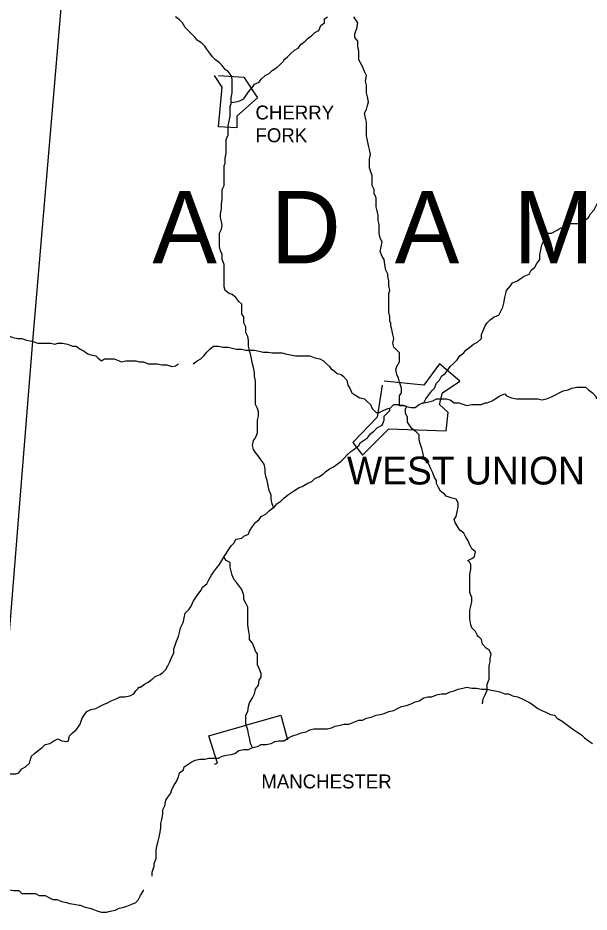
# Model space of a CAD drawing. Extents: x 0 to 34, y 0 to 22.
# Drawn here: x 3.578 to 4.378, y 16.05 to 17.302 of the extents above; entities that cross this region are included whole.
import ezdxf

# ---------------------------------------------------------------- set-up
doc = ezdxf.new("R2010")
doc.units = 0
doc.layers.add('Default', color=7, linetype='Continuous')
doc.layers.add('TR_Turning_Path1', color=7, linetype='Continuous')

msp = doc.modelspace()

# ---------------------------------------------------------------- linework, layer by layer
at = {"layer": 'Default'}
for points in [[(3.6789, 17.7858), (3.6516, 17.4749), (3.5985, 16.8491), (3.5507, 16.2615), (3.5412, 16.0883), (3.5398, 16.0652)], [(3.8766, 17.1832), (3.8766, 17.19), (3.878, 17.1968), (3.878, 17.2023), (3.878, 17.2091), (3.878, 17.2159), (3.8766, 17.2213), (3.8725, 17.2268), (3.8684, 17.2295), (3.8643, 17.235), (3.8602, 17.2391), (3.8548, 17.2432), (3.8507, 17.2473), (3.8452, 17.2541), (3.8425, 17.2582), (3.8398, 17.2623), (3.8357, 17.2663), (3.8289, 17.2704), (3.8261, 17.2745), (3.8207, 17.28), (3.8166, 17.2841), (3.8125, 17.2882), (3.8084, 17.295), (3.8043, 17.2991), (3.7989, 17.3032)], [(3.9502, 17.2432), (3.9557, 17.2473), (3.9598, 17.2513), (3.9652, 17.2568), (3.9707, 17.2595), (3.9748, 17.265), (3.9802, 17.2691), (3.9843, 17.2732), (3.9898, 17.2772), (3.9938, 17.2813), (3.9993, 17.2841), (4.002, 17.2909), (4.0075, 17.295), (4.0075, 17.3004), (4.0116, 17.3032)], [(4.0661, 17.1559), (4.0647, 17.1614), (4.0634, 17.1682), (4.0661, 17.1736), (4.0675, 17.1791), (4.0688, 17.1845), (4.0675, 17.1914), (4.0661, 17.1968), (4.0661, 17.2023), (4.0661, 17.2077), (4.0647, 17.2132), (4.0661, 17.2213), (4.0634, 17.2268), (4.0607, 17.2336), (4.0579, 17.2391), (4.0552, 17.2432), (4.0552, 17.25), (4.0552, 17.2554), (4.0538, 17.2623), (4.0538, 17.2691), (4.0497, 17.2745), (4.0497, 17.28), (4.0525, 17.2868), (4.0538, 17.295), (4.0511, 17.2991), (4.0484, 17.3032)], [(3.8766, 17.1832), (3.8834, 17.1845), (3.8889, 17.1859), (3.8943, 17.1886), (3.897, 17.1927), (3.9011, 17.1982), (3.9066, 17.205), (3.9093, 17.2091), (3.9161, 17.2118), (3.9189, 17.2159), (3.9243, 17.2213), (3.9298, 17.2241), (3.9339, 17.2282), (3.9407, 17.2323), (3.9448, 17.2363), (3.9502, 17.2418), (3.9502, 17.2432)], [(3.8589, 17.2213), (3.8943, 17.2186), (3.9134, 17.19), (3.8848, 17.1641), (3.8848, 17.1477), (3.8589, 17.1491), (3.8643, 17.205), (3.8534, 17.2213)], [(3.8602, 17.0005), (3.863, 17.0059), (3.8643, 17.0114), (3.863, 17.0168), (3.8616, 17.0223), (3.8616, 17.0277), (3.863, 17.0346), (3.863, 17.0414), (3.8643, 17.0482), (3.8643, 17.055), (3.8643, 17.0618), (3.867, 17.0673), (3.867, 17.0741), (3.867, 17.0809), (3.867, 17.0877), (3.867, 17.0946), (3.8684, 17.0986), (3.8684, 17.1055), (3.8698, 17.1123), (3.8698, 17.1191), (3.8698, 17.1245), (3.8698, 17.1314), (3.8725, 17.1382), (3.8725, 17.145), (3.8725, 17.1505), (3.8739, 17.1573), (3.8752, 17.1641), (3.8752, 17.1695), (3.8752, 17.1777), (3.8766, 17.1818), (3.8766, 17.1832)], [(4.077, 17.055), (4.077, 17.0618), (4.0743, 17.0673), (4.0743, 17.0741), (4.0743, 17.0809), (4.0716, 17.0877), (4.0702, 17.0918), (4.0702, 17.0986), (4.0702, 17.1041), (4.0716, 17.1109), (4.0702, 17.1177), (4.0688, 17.1232), (4.0675, 17.13), (4.0661, 17.1368), (4.0661, 17.1423), (4.0661, 17.1491), (4.0661, 17.1545), (4.0661, 17.1545), (4.0661, 17.1559)], [(4.3415, 17.0087), (4.3483, 17.0127), (4.3524, 17.0141), (4.3606, 17.0141), (4.3661, 17.0141), (4.3715, 17.0182), (4.377, 17.0223), (4.3797, 17.0277), (4.3851, 17.0332), (4.3879, 17.0387), (4.3906, 17.0441), (4.3933, 17.0496), (4.3988, 17.0536), (4.4029, 17.0577), (4.407, 17.0632), (4.4097, 17.07), (4.4138, 17.0741), (4.4179, 17.0796), (4.422, 17.085), (4.422, 17.0891)], [(4.0961, 16.9432), (4.0934, 16.9487), (4.092, 16.9568), (4.0907, 16.9637), (4.0879, 16.9678), (4.0852, 16.9746), (4.0866, 16.9814), (4.0879, 16.9882), (4.0852, 16.9937), (4.0838, 17.0005), (4.0838, 17.0059), (4.0838, 17.0127), (4.0825, 17.0182), (4.0825, 17.025), (4.0811, 17.0318), (4.0797, 17.0373), (4.0797, 17.0441), (4.0797, 17.0496), (4.0784, 17.0536), (4.077, 17.055)], [(3.9025, 16.8369), (3.9011, 16.8423), (3.9011, 16.8505), (3.8998, 16.856), (3.897, 16.8614), (3.897, 16.8696), (3.8943, 16.875), (3.8943, 16.8832), (3.8916, 16.8873), (3.8916, 16.8941), (3.8916, 16.9009), (3.8875, 16.905), (3.8834, 16.9105), (3.878, 16.9146), (3.8739, 16.9159), (3.8684, 16.92), (3.867, 16.9255), (3.867, 16.9323), (3.867, 16.9391), (3.867, 16.9446), (3.867, 16.9514), (3.867, 16.9568), (3.8643, 16.9637), (3.8643, 16.9705), (3.8616, 16.9759), (3.8602, 16.9814), (3.8602, 16.9882), (3.8602, 16.995), (3.8602, 16.9991), (3.8602, 17.0005)], [(4.3088, 16.9705), (4.3102, 16.9773), (4.3115, 16.9841), (4.3143, 16.9896), (4.317, 16.995), (4.3197, 17.0005), (4.3252, 17.0005), (4.3333, 17.0046), (4.3374, 17.0073), (4.3415, 17.0087), (4.3415, 17.0087)], [(4.2447, 16.8832), (4.2515, 16.8859), (4.2543, 16.8914), (4.257, 16.8969), (4.2584, 16.9023), (4.2597, 16.9105), (4.2611, 16.9159), (4.2624, 16.92), (4.2679, 16.9269), (4.2706, 16.9309), (4.2774, 16.9337), (4.2815, 16.9364), (4.287, 16.9405), (4.2938, 16.9432), (4.2965, 16.9487), (4.302, 16.9528), (4.3047, 16.9582), (4.3088, 16.9637), (4.3088, 16.9691), (4.3088, 16.9705), (4.3088, 16.9705)], [(4.0988, 16.8764), (4.0988, 16.8832), (4.0975, 16.89), (4.0975, 16.8969), (4.0975, 16.9023), (4.0975, 16.9078), (4.0975, 16.9159), (4.0988, 16.92), (4.0975, 16.9269), (4.0975, 16.9337), (4.0961, 16.9405), (4.0961, 16.9432), (4.0961, 16.9432)], [(3.5098, 16.8778), (3.5167, 16.8737), (3.5235, 16.8709), (3.5289, 16.8669), (3.5344, 16.8669), (3.5398, 16.8641), (3.5466, 16.8614), (3.5521, 16.86), (3.5589, 16.8587), (3.5644, 16.8573), (3.5712, 16.8546), (3.578, 16.8532), (3.5835, 16.8532), (3.5903, 16.8505), (3.5971, 16.8491), (3.5985, 16.8491)], [(4.1125, 16.7591), (4.1125, 16.766), (4.1125, 16.7728), (4.1152, 16.7769), (4.1152, 16.7837), (4.1125, 16.7919), (4.1111, 16.7973), (4.1084, 16.8028), (4.107, 16.8096), (4.1084, 16.8137), (4.1125, 16.8205), (4.1125, 16.826), (4.1125, 16.8328), (4.1084, 16.8369), (4.1043, 16.841), (4.1029, 16.8464), (4.1043, 16.8532), (4.1029, 16.8587), (4.1016, 16.8655), (4.1002, 16.8709), (4.1002, 16.875), (4.0988, 16.8764)], [(4.1466, 16.7632), (4.1493, 16.7687), (4.1534, 16.7741), (4.1575, 16.7796), (4.1615, 16.7837), (4.1643, 16.7905), (4.1684, 16.7946), (4.1711, 16.8001), (4.1765, 16.8041), (4.1806, 16.8096), (4.1834, 16.8137), (4.1875, 16.8178), (4.1929, 16.8232), (4.197, 16.8287), (4.2025, 16.8328), (4.2052, 16.8369), (4.2106, 16.841), (4.2161, 16.845), (4.2215, 16.8478), (4.227, 16.8532), (4.227, 16.8587), (4.2297, 16.8641), (4.2324, 16.8709), (4.2352, 16.875), (4.2393, 16.8791), (4.2447, 16.8832), (4.2447, 16.8832), (4.2447, 16.8832)], [(3.5985, 16.8491), (3.6053, 16.8464), (3.6107, 16.8464), (3.6175, 16.8464), (3.6244, 16.8464), (3.6298, 16.845), (3.6339, 16.8464), (3.6407, 16.8464), (3.6475, 16.845), (3.6544, 16.8423), (3.6598, 16.8423), (3.6653, 16.8382), (3.6707, 16.8355), (3.6762, 16.8314), (3.6803, 16.83), (3.6871, 16.8287), (3.6898, 16.826), (3.6953, 16.8219), (3.6993, 16.8246), (3.7062, 16.8246), (3.713, 16.8246), (3.7198, 16.8219), (3.7225, 16.8205)], [(3.8234, 16.8178), (3.8289, 16.8219), (3.8343, 16.8246), (3.8384, 16.8287), (3.8425, 16.8341), (3.8466, 16.8382), (3.8521, 16.8423), (3.8589, 16.8423), (3.8657, 16.841), (3.8725, 16.841), (3.878, 16.8396), (3.8848, 16.8382), (3.8916, 16.8382), (3.897, 16.8369), (3.9011, 16.8369), (3.9025, 16.8369)], [(3.9134, 16.7305), (3.9134, 16.7387), (3.9148, 16.7442), (3.9148, 16.751), (3.9134, 16.7551), (3.9107, 16.7605), (3.9107, 16.7687), (3.9107, 16.7741), (3.9107, 16.781), (3.9107, 16.7878), (3.9107, 16.7932), (3.9093, 16.8001), (3.9093, 16.8055), (3.908, 16.8123), (3.9066, 16.8178), (3.9052, 16.8246), (3.9039, 16.8314), (3.9025, 16.8355), (3.9025, 16.8369)], [(3.9025, 16.8369), (3.9093, 16.8369), (3.9161, 16.8355), (3.9216, 16.8341), (3.9284, 16.8341), (3.9339, 16.8328), (3.942, 16.8328), (3.9475, 16.8328), (3.9529, 16.8314), (3.9598, 16.83), (3.9666, 16.8287), (3.9734, 16.8287), (3.9802, 16.8287), (3.987, 16.8287), (3.987, 16.8287)], [(3.7225, 16.8205), (3.7293, 16.8219), (3.7362, 16.8219), (3.743, 16.8219), (3.7484, 16.8205), (3.7539, 16.8205), (3.7607, 16.8178), (3.7689, 16.8178), (3.773, 16.8178), (3.7798, 16.8164), (3.7866, 16.8164), (3.7934, 16.8137), (3.7989, 16.815), (3.803, 16.8178), (3.803, 16.8178)], [(3.987, 16.8287), (3.9938, 16.826), (4.0007, 16.8246), (4.0061, 16.8219), (4.0102, 16.8178), (4.0143, 16.8137), (4.017, 16.8096), (4.0184, 16.8096)], [(4.0184, 16.8096), (4.0252, 16.8041), (4.0307, 16.8028), (4.0334, 16.8001), (4.0388, 16.7946), (4.0402, 16.7878), (4.0429, 16.7837), (4.0457, 16.7769), (4.0497, 16.7741), (4.0566, 16.7701), (4.0634, 16.7687), (4.0675, 16.7646), (4.0716, 16.7605), (4.0743, 16.7551), (4.0797, 16.7496), (4.0838, 16.7496), (4.0893, 16.7523), (4.0961, 16.7551), (4.0988, 16.7551)], [(4.0879, 16.7878), (4.0811, 16.7428), (4.047, 16.7073), (4.0607, 16.6896), (4.0975, 16.7264), (4.1779, 16.7237), (4.1806, 16.7496), (4.1684, 16.7605), (4.1725, 16.7769), (4.197, 16.7932), (4.1684, 16.8178), (4.1466, 16.7878), (4.0907, 16.7932)], [(4.287, 16.7687), (4.2924, 16.7687), (4.3006, 16.7687), (4.3061, 16.7687), (4.3115, 16.7673), (4.3183, 16.7687), (4.3252, 16.7714), (4.3306, 16.7741), (4.3361, 16.7769), (4.3415, 16.7796), (4.3483, 16.781), (4.3538, 16.7837), (4.3606, 16.7851), (4.3674, 16.7851), (4.3729, 16.7851), (4.377, 16.781), (4.3824, 16.7769), (4.3879, 16.7714), (4.3879, 16.7687)], [(4.2352, 16.7632), (4.242, 16.766), (4.2461, 16.7687), (4.2529, 16.7728), (4.2597, 16.7755), (4.2624, 16.7728), (4.2693, 16.7701), (4.2761, 16.7687), (4.2815, 16.7687), (4.287, 16.7687)], [(4.0988, 16.7551), (4.1043, 16.7605), (4.1097, 16.7605), (4.1125, 16.7591)], [(4.0988, 16.7551), (4.1043, 16.7605), (4.1097, 16.7605), (4.1125, 16.7591)], [(4.122, 16.7578), (4.1288, 16.7564), (4.1343, 16.7564), (4.1397, 16.7605), (4.1452, 16.7632), (4.1466, 16.7632)], [(4.122, 16.7578), (4.1288, 16.7564), (4.1343, 16.7564), (4.1397, 16.7605), (4.1452, 16.7632), (4.1466, 16.7632)], [(4.1466, 16.7632), (4.1534, 16.7646), (4.1588, 16.766), (4.1643, 16.7687), (4.1711, 16.7687), (4.1779, 16.7687), (4.1834, 16.7673), (4.1888, 16.7632), (4.1956, 16.7632), (4.2025, 16.7605), (4.2065, 16.7591), (4.2134, 16.7605), (4.2202, 16.7605), (4.227, 16.7605), (4.2324, 16.7632), (4.2352, 16.7632), (4.2352, 16.7632)], [(3.9366, 16.616), (3.9407, 16.6214), (3.9461, 16.6255), (3.9502, 16.6296), (3.9557, 16.6337), (3.9598, 16.6364), (3.9652, 16.6405), (3.972, 16.6446), (3.9761, 16.646), (3.9829, 16.6501), (3.9898, 16.6528), (3.9938, 16.6569), (3.9993, 16.6596), (4.0061, 16.6637), (4.0088, 16.6664), (4.0143, 16.6705), (4.0198, 16.6733), (4.0252, 16.6773), (4.0307, 16.6814), (4.0348, 16.6855), (4.0388, 16.6896), (4.0443, 16.6951), (4.0484, 16.6978), (4.0552, 16.7032), (4.0579, 16.7073), (4.0634, 16.7114), (4.0675, 16.7142), (4.0716, 16.7196), (4.077, 16.7237), (4.0811, 16.7278), (4.0879, 16.7319), (4.0907, 16.7387), (4.0907, 16.7442), (4.0947, 16.7482), (4.0988, 16.7523), (4.0988, 16.7551), (4.0988, 16.7551)], [(4.1125, 16.7591), (4.1179, 16.7591), (4.122, 16.7578)], [(4.1125, 16.7591), (4.1179, 16.7591), (4.122, 16.7578)], [(4.122, 16.7578), (4.1179, 16.7591), (4.1125, 16.7591)], [(4.1643, 16.6542), (4.1615, 16.6583), (4.1588, 16.6651), (4.1561, 16.6705), (4.1534, 16.6773), (4.1493, 16.6814), (4.1466, 16.6869), (4.1452, 16.6937), (4.1438, 16.6992), (4.1411, 16.706), (4.1397, 16.7114), (4.1397, 16.7182), (4.1356, 16.7223), (4.1302, 16.7264), (4.1275, 16.7305), (4.1234, 16.736), (4.1234, 16.7428), (4.1206, 16.7482), (4.1206, 16.7551), (4.122, 16.7564), (4.122, 16.7578)], [(3.9366, 16.616), (3.9339, 16.6214), (3.9325, 16.6283), (3.9325, 16.6337), (3.9298, 16.6405), (3.9284, 16.6473), (3.927, 16.6542), (3.9257, 16.6583), (3.9243, 16.6651), (3.9243, 16.6705), (3.9229, 16.6773), (3.9189, 16.6828), (3.9161, 16.6869), (3.9107, 16.6937), (3.908, 16.6978), (3.9066, 16.7032), (3.908, 16.7101), (3.9107, 16.7142), (3.9134, 16.721), (3.9134, 16.7264), (3.9134, 16.7305), (3.9134, 16.7305)], [(4.2079, 16.5424), (4.2134, 16.5451), (4.2174, 16.5478), (4.2188, 16.5546), (4.2134, 16.5587), (4.2106, 16.5642), (4.2079, 16.571), (4.2052, 16.5751), (4.2025, 16.5805), (4.197, 16.5846), (4.1943, 16.5887), (4.1902, 16.5955), (4.1888, 16.5996), (4.1915, 16.6037), (4.1929, 16.6105), (4.1943, 16.6174), (4.1943, 16.6228), (4.1915, 16.6283), (4.1861, 16.6296), (4.1779, 16.6324), (4.1752, 16.6351), (4.1697, 16.6392), (4.167, 16.6446), (4.1643, 16.6501), (4.1643, 16.6542), (4.1643, 16.6542), (4.1643, 16.6542)], [(3.867, 16.5478), (3.8698, 16.5519), (3.8739, 16.5587), (3.8766, 16.5628), (3.8807, 16.5669), (3.8834, 16.5724), (3.8916, 16.5737), (3.8943, 16.5765), (3.9011, 16.5792), (3.9025, 16.5833), (3.9066, 16.5901), (3.9107, 16.5955), (3.9161, 16.5996), (3.9189, 16.6037), (3.9257, 16.6078), (3.9298, 16.6119), (3.9352, 16.616), (3.9366, 16.616)], [(3.867, 16.5478), (3.8698, 16.5519), (3.8739, 16.5587), (3.8766, 16.5628), (3.8807, 16.5669), (3.8834, 16.5724), (3.8916, 16.5737), (3.8943, 16.5765), (3.9011, 16.5792), (3.9025, 16.5833), (3.9066, 16.5901), (3.9107, 16.5955), (3.9161, 16.5996), (3.9189, 16.6037), (3.9257, 16.6078), (3.9298, 16.6119), (3.9352, 16.616), (3.9366, 16.616)], [(3.8098, 16.4565), (3.8111, 16.4619), (3.8125, 16.4687), (3.818, 16.4742), (3.8207, 16.4783), (3.8234, 16.4851), (3.8261, 16.4892), (3.8289, 16.4933), (3.8343, 16.5001), (3.8371, 16.5056), (3.8425, 16.5096), (3.8452, 16.5151), (3.8493, 16.5219), (3.8521, 16.526), (3.8561, 16.5315), (3.8602, 16.5369), (3.867, 16.5478)], [(3.9066, 16.2806), (3.9039, 16.286), (3.9025, 16.2942), (3.9011, 16.2997), (3.8998, 16.3051), (3.897, 16.3133), (3.897, 16.3188), (3.897, 16.3256), (3.8998, 16.331), (3.9011, 16.3379), (3.9025, 16.3433), (3.9066, 16.3501), (3.9093, 16.3556), (3.9107, 16.3624), (3.9148, 16.3678), (3.9161, 16.3747), (3.9189, 16.3788), (3.9189, 16.3842), (3.9161, 16.391), (3.9134, 16.3965), (3.9134, 16.4033), (3.9134, 16.4115), (3.9107, 16.4156), (3.9093, 16.4197), (3.9066, 16.4265), (3.9025, 16.4319), (3.9025, 16.4374), (3.9011, 16.4456), (3.8998, 16.4524), (3.8998, 16.4565), (3.8998, 16.4633), (3.8998, 16.4701), (3.8998, 16.4769), (3.897, 16.4824), (3.8943, 16.4878), (3.8943, 16.4933), (3.8916, 16.5015), (3.8889, 16.5056), (3.8848, 16.511), (3.8807, 16.5151), (3.878, 16.5219), (3.8766, 16.5274), (3.8752, 16.5328), (3.8752, 16.5396), (3.8698, 16.5424), (3.867, 16.5465), (3.867, 16.5478)], [(4.2134, 16.4851), (4.2134, 16.4906), (4.2106, 16.4974), (4.2106, 16.5015), (4.2106, 16.5069), (4.2106, 16.511), (4.2106, 16.5178), (4.2106, 16.5233), (4.212, 16.5301), (4.212, 16.5369), (4.2106, 16.5396), (4.2079, 16.5424)], [(4.2215, 16.4374), (4.2188, 16.4428), (4.2134, 16.4483), (4.212, 16.4524), (4.2106, 16.4606), (4.2106, 16.466), (4.2106, 16.4728), (4.212, 16.4783), (4.2134, 16.4851), (4.2134, 16.4851)], [(3.7498, 16.3651), (3.7552, 16.3692), (3.7607, 16.3719), (3.7662, 16.376), (3.7702, 16.3801), (3.7771, 16.3828), (3.7812, 16.3856), (3.7852, 16.3897), (3.788, 16.3951), (3.7907, 16.4006), (3.7934, 16.4074), (3.7962, 16.4128), (3.7962, 16.4183), (3.7989, 16.4251), (3.8002, 16.4292), (3.803, 16.436), (3.8043, 16.4415), (3.8057, 16.4483), (3.8084, 16.4537), (3.8098, 16.4565), (3.8098, 16.4565)], [(4.2352, 16.3624), (4.2352, 16.3692), (4.2379, 16.376), (4.2379, 16.3815), (4.2379, 16.3869), (4.2379, 16.3951), (4.2393, 16.4006), (4.2393, 16.4047), (4.2406, 16.4115), (4.2379, 16.4169), (4.2338, 16.4197), (4.2284, 16.4251), (4.227, 16.4319), (4.2229, 16.436), (4.2215, 16.436), (4.2215, 16.4374)], [(3.6489, 16.2901), (3.6503, 16.2969), (3.6544, 16.301), (3.6598, 16.3051), (3.6625, 16.3092), (3.6653, 16.3133), (3.668, 16.3215), (3.6707, 16.3256), (3.6748, 16.331), (3.6803, 16.3338), (3.6871, 16.3351), (3.6925, 16.3379), (3.698, 16.3406), (3.7034, 16.3433), (3.7089, 16.346), (3.7157, 16.3488), (3.7212, 16.3515), (3.728, 16.3515), (3.7348, 16.3528), (3.7403, 16.3556), (3.743, 16.3597), (3.7471, 16.3638), (3.7471, 16.3651), (3.7498, 16.3651)], [(3.9066, 16.2806), (3.9134, 16.282), (3.9189, 16.2847), (3.9257, 16.2847), (3.9325, 16.286), (3.9379, 16.2888), (3.9434, 16.2901), (3.9502, 16.2901), (3.957, 16.2942), (3.9625, 16.2969), (3.9679, 16.2983), (3.9748, 16.301), (3.9816, 16.3024), (3.987, 16.3051), (3.9925, 16.3065), (3.9979, 16.3065), (4.0061, 16.3065), (4.0116, 16.3065), (4.017, 16.3079), (4.0225, 16.3106), (4.0293, 16.3119), (4.0348, 16.3133), (4.0416, 16.3133), (4.0484, 16.316), (4.0552, 16.3188), (4.0607, 16.3188), (4.0661, 16.3215), (4.0729, 16.3229), (4.0797, 16.3256), (4.0852, 16.3269), (4.0907, 16.3283), (4.0975, 16.331), (4.1043, 16.3324), (4.1097, 16.3351), (4.1152, 16.3379), (4.122, 16.3392), (4.1288, 16.3419), (4.1343, 16.3447), (4.1397, 16.346), (4.1466, 16.3501), (4.152, 16.3515), (4.1575, 16.3515), (4.1643, 16.3542), (4.1711, 16.3556), (4.1779, 16.3556), (4.1834, 16.3583), (4.1888, 16.3597), (4.1943, 16.3624), (4.2011, 16.3638), (4.2065, 16.3651), (4.2134, 16.3638), (4.2202, 16.3638), (4.227, 16.3624), (4.2324, 16.3624), (4.2338, 16.3624), (4.2352, 16.3624)], [(4.2284, 16.3419), (4.2297, 16.3488), (4.2324, 16.3542), (4.2352, 16.361), (4.2352, 16.3624)], [(4.2352, 16.3624), (4.2406, 16.361), (4.2461, 16.3597), (4.2529, 16.3583), (4.2597, 16.3556), (4.2652, 16.3556), (4.2706, 16.3528), (4.2774, 16.3515), (4.2843, 16.3488), (4.2897, 16.346), (4.2952, 16.3433), (4.3006, 16.3392), (4.3061, 16.3351), (4.3115, 16.3324), (4.3183, 16.3297), (4.3238, 16.3269), (4.3292, 16.3256), (4.3333, 16.3215), (4.3402, 16.3174), (4.3456, 16.3133), (4.3511, 16.3092), (4.3565, 16.3051), (4.3606, 16.3024), (4.3674, 16.2983), (4.3715, 16.2942), (4.377, 16.2901), (4.3824, 16.286)], [(3.8534, 16.2574), (3.8575, 16.2588), (3.8452, 16.2969), (3.9461, 16.3256), (3.9557, 16.2915)], [(3.5507, 16.2615), (3.5507, 16.2533), (3.5507, 16.2479), (3.5562, 16.2451), (3.563, 16.2438), (3.5698, 16.2438), (3.5753, 16.2438), (3.5794, 16.2451), (3.5835, 16.2506), (3.5889, 16.2533), (3.5944, 16.2588), (3.5957, 16.2642), (3.5971, 16.2683), (3.6012, 16.2724), (3.6066, 16.2765), (3.6121, 16.2806), (3.6162, 16.2847), (3.623, 16.286), (3.6285, 16.2901), (3.6339, 16.2929), (3.6394, 16.2901), (3.6462, 16.2888), (3.6489, 16.2901), (3.6489, 16.2901)], [(3.8111, 16.2533), (3.8166, 16.2574), (3.8207, 16.2601), (3.8261, 16.2629), (3.833, 16.2642), (3.8398, 16.2642), (3.8452, 16.2656), (3.8521, 16.2656), (3.8589, 16.2656), (3.8643, 16.2683), (3.8698, 16.2697), (3.8766, 16.271), (3.882, 16.2724), (3.8875, 16.2765), (3.8943, 16.2779), (3.9011, 16.2779), (3.9066, 16.2806), (3.9066, 16.2806)], [(3.7662, 16.1006), (3.7662, 16.1061), (3.7689, 16.1143), (3.7689, 16.1183), (3.7716, 16.1252), (3.7716, 16.1306), (3.7716, 16.1374), (3.773, 16.1442), (3.7743, 16.1497), (3.7757, 16.1552), (3.7771, 16.162), (3.7784, 16.1688), (3.7784, 16.1742), (3.7798, 16.1797), (3.7812, 16.1879), (3.7812, 16.1933), (3.7839, 16.1988), (3.7852, 16.207), (3.788, 16.2111), (3.7921, 16.2165), (3.7934, 16.222), (3.7975, 16.2288), (3.8002, 16.2329), (3.803, 16.2397), (3.8043, 16.2451), (3.8098, 16.2492), (3.8111, 16.2533), (3.8111, 16.2533)], [(3.5412, 16.0883), (3.548, 16.087), (3.5535, 16.0843), (3.5589, 16.0829), (3.5657, 16.0815), (3.5726, 16.0802), (3.5794, 16.0802), (3.5835, 16.0761), (3.5903, 16.0761), (3.5971, 16.0761), (3.6025, 16.0761), (3.608, 16.0733), (3.6162, 16.0733), (3.6216, 16.0706), (3.6271, 16.0679), (3.6325, 16.0679), (3.6394, 16.0652), (3.6462, 16.0638), (3.6503, 16.0624), (3.6571, 16.0611), (3.6639, 16.0597), (3.6653, 16.0597), (3.6653, 16.0597)], [(3.6653, 16.0597), (3.6721, 16.057), (3.6789, 16.0556), (3.683, 16.0543), (3.6898, 16.0515), (3.6953, 16.0502), (3.7021, 16.0502), (3.7075, 16.0515), (3.7143, 16.0529), (3.7198, 16.0556), (3.7266, 16.057), (3.7307, 16.0584), (3.7375, 16.0611), (3.743, 16.0638), (3.7471, 16.0679), (3.7498, 16.0733), (3.7539, 16.0802), (3.7539, 16.0802), (3.7539, 16.0815)]]:
    msp.add_lwpolyline(points, dxfattribs=at)

# ---------------------------------------------------------------- texts
for s, height, p in [('CHERRY', 0.0195, (3.9107, 17.1596)), ('FORK', 0.0195, (3.9107, 17.1278)), ('WEST UNION', 0.039, (4.0388, 16.6487)), ('MANCHESTER', 0.0195, (3.9189, 16.2233))]:
    msp.add_text(s, height=height, dxfattribs=at).set_placement(p)
at = {"layer": 'TR_Turning_Path1'}
msp.add_text('A  D  A  M  S', height=0.101489, dxfattribs=at).set_placement((3.7663, 16.9582))

doc.saveas('drawing.dxf')
